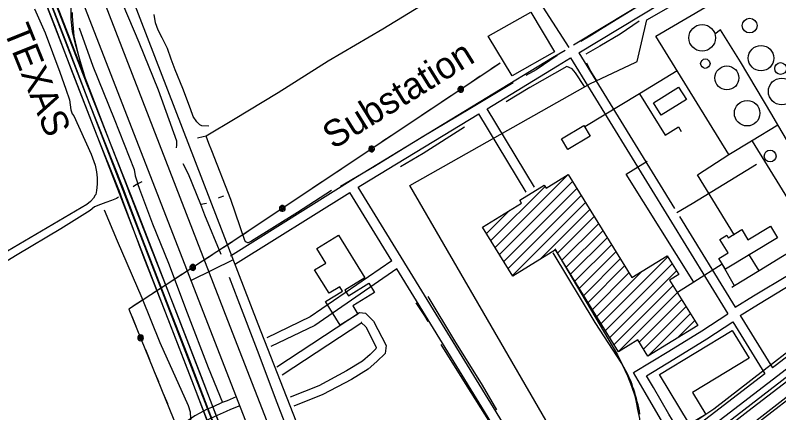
# Model space of a CAD drawing. Extents: x 3297753 to 3335611, y 652252 to 677623.
# Drawn here: x 3303720 to 3306096, y 667532 to 668771 of the extents above; entities that cross this region are included whole.
import ezdxf

# ---------------------------------------------------------------- set-up
doc = ezdxf.new("R2010")
doc.units = 0
for name, color, linetype in [('V-BLDG-OTLN', 7, 'Continuous'), ('V-DOMW-TANK', 7, 'Continuous'), ('V-DTCH-CNTR', 7, 'Continuous'), ('V-RAIL-IDEN', 7, 'Continuous'), ('V-RAIL-TRAK', 7, 'Continuous'), ('V-ROAD-CNTR', 7, 'Continuous'), ('V-SITE-OTLN', 7, 'Continuous'), ('V-SITE-OTLN-IDEN', 7, 'Continuous'), ('V-TOPO-SHOR', 7, 'Continuous'), ('V-UTIL-LINE', 7, 'Continuous')]:
    doc.layers.add(name, color=color, linetype=linetype)

msp = doc.modelspace()

# ---------------------------------------------------------------- linework, layer by layer
at = {"layer": 'V-BLDG-OTLN'}
for p, q in [((3305214, 668047.3), (3305440.9, 668274.2)), ((3305227.5, 668025.4), (3305454.5, 668252.4)), ((3305200.5, 668069.1), (3305369, 668237.6)), ((3305241, 668003.6), (3305468, 668230.6)), ((3305254.5, 667981.7), (3305481.5, 668208.7)), ((3305290.2, 668194.2), (3305290.4, 668194.4)), ((3305268, 667959.9), (3305495, 668186.9)), ((3305187, 668091), (3305259.2, 668163.2)), ((3305354.9, 668011.5), (3305508.5, 668165)), ((3305408, 668029.2), (3305522, 668143.2)), ((3305421.5, 668007.3), (3305535.5, 668121.3)), ((3305435, 667985.5), (3305549, 668099.5)), ((3305448.5, 667963.7), (3305562.5, 668077.7)), ((3305462.1, 667941.8), (3305576.1, 668055.8)), ((3305475.6, 667920), (3305589.6, 668034)), ((3305489.1, 667898.1), (3305603.1, 668012.1)), ((3305543.1, 667810.7), (3305750.8, 668018.4)), ((3305502.6, 667876.3), (3305616.6, 667990.3)), ((3305556.6, 667788.9), (3305764.3, 667996.6)), ((3305516.1, 667854.4), (3305630.1, 667968.4)), ((3305529.6, 667832.6), (3305669.8, 667972.7)), ((3305570.1, 667767), (3305777.8, 667974.7)), ((3305583.6, 667745.2), (3305767.2, 667928.8)), ((3305597.1, 667723.3), (3305780.8, 667907)), ((3305661.8, 667752.6), (3305794.3, 667885.1)), ((3305675.3, 667730.8), (3305807.8, 667863.3)), ((3305688.8, 667708.9), (3305821.3, 667841.4)), ((3305780.1, 667764.9), (3305834.8, 667819.6))]:
    msp.add_line(p, q, dxfattribs=at)
for points in [[(3305706.2, 668497.7), (3305784.5, 668546.8), (3305808.8, 668508), (3305730.6, 668458.9)], [(3305420, 668385.5), (3305489.1, 668427), (3305509.2, 668393.6), (3305440.1, 668352.1)], [(3305597.7, 667722.5), (3305401.3, 668040.1), (3305269, 667958.3), (3305174.6, 668110.9), (3305295.5, 668185.7), (3305290.2, 668194.3), (3305366.6, 668241.5), (3305372.5, 668231.9), (3305441, 668274.3), (3305639.1, 667953.8), (3305748.8, 668021.6), (3305784.9, 667963.2), (3305756.7, 667945.8), (3305844.1, 667804.5), (3305689, 667708.6), (3305657.5, 667759.5)], [(3306092.6, 668077.6), (3305930.4, 667979.6), (3305910.3, 668012.9), (3305938.6, 668030.1), (3305913.2, 668072.2), (3305934.8, 668085.2), (3305939.4, 668077.5), (3305981.2, 668102.7), (3306000.4, 668070.8), (3306071, 668113.4)], [(3304726.2, 668085.6), (3304807.9, 667952.7), (3304745.6, 667914.3), (3304756.5, 667896.6), (3304819.9, 667935.6), (3304837.6, 667906.8), (3304770, 667865.2), (3304785.8, 667839.4), (3304731, 667805.7), (3304685.9, 667879.1), (3304738.4, 667911.4), (3304729.9, 667925.1), (3304696.4, 667904.5), (3304651.6, 667977.3), (3304686.3, 667998.7), (3304658.5, 668044)], [(3305818.8, 667496.6), (3305725.2, 667651.3), (3305951.8, 667788.4), (3306003.8, 667702.4), (3305827.6, 667595.8), (3305869.2, 667527.1)]]:
    msp.add_lwpolyline(points, close=True, dxfattribs=at)
at = {"layer": 'V-DOMW-TANK'}
for centre, radius in [((3305858, 668700.3), 41.6), ((3306005.8, 668738.4), 22.9), ((3306041.3, 668636.9), 39.7), ((3305867.8, 668619.8), 14.6), ((3306102.1, 668604.6), 18.4), ((3305935, 668575.3), 37.2), ((3306105.9, 668533.1), 41.8), ((3305998, 668465.4), 39.7), ((3306069.6, 668332), 18.4)]:
    msp.add_circle(centre, radius, dxfattribs=at)
at = {"layer": 'V-DTCH-CNTR'}
for points in [[(3303779.4, 668790.4), (3303812.6, 668716.3), (3303858.2, 668593.6), (3303877, 668539.8), (3303888.3, 668507), (3303892.7, 668476.2), (3303896.5, 668463.2), (3303901.5, 668457.1), (3303956, 668338.2), (3303968, 668303.4), (3303972.7, 668282.9), (3303974.7, 668264.4), (3303974.6, 668244.4), (3303972.4, 668225), (3303970, 668212.6), (3303968, 668209.8), (3303963.4, 668201.3), (3303953.4, 668190), (3303942.7, 668180.8), (3303659, 668014.6)], [(3304322.1, 668424.9), (3304300.8, 668425.7), (3304294.5, 668428.9), (3304284.5, 668438.3), (3304273.7, 668455.1), (3304264.8, 668479), (3304240.9, 668542.3), (3304217.8, 668600.8), (3304205.1, 668634.1), (3304193.1, 668666.8), (3304177, 668700.1), (3304164.6, 668724.5), (3304156.4, 668747), (3304152.2, 668773)], [(3304258.4, 667464.2), (3304267.1, 667496.1), (3304265.3, 667534.6), (3304259.2, 667553.8), (3304170.7, 667750.2), (3304114.3, 667889.8), (3304038.1, 668067.3), (3303997.4, 668163.9)]]:
    msp.add_lwpolyline(points, dxfattribs=at)
at = {"layer": 'V-RAIL-TRAK'}
for points in [[(3304384.4, 667339.6), (3304326.4, 667483.4), (3304269.2, 667633.7), (3304197.2, 667818.4), (3304121.2, 668014), (3304054.7, 668192.6), (3304042.9, 668224.2), (3304040.2, 668231.6), (3303974.5, 668395.2), (3303897.6, 668592.6), (3303841.3, 668740.2), (3303767.3, 668931.7)], [(3304416.9, 667342.4), (3304355.9, 667496.6), (3304299.2, 667644.1), (3304223.1, 667842.9), (3304145.2, 668040.3), (3304080.7, 668204.6), (3304079.7, 668207.1), (3304065.1, 668245.1), (3304016.1, 668371.1), (3303940.5, 668568.6), (3303928.3, 668599.8), (3303865.6, 668760.1), (3303793, 668948.4)], [(3303794.8, 668900.7), (3303880.9, 668677), (3303949, 668499.5), (3304026.8, 668303.5), (3304052, 668238), (3304066.9, 668199.7), (3304103.4, 668104.7), (3304184.9, 667892.8), (3304260.9, 667698.1), (3304336, 667502.5), (3304401, 667335.9)], [(3303896.3, 668779.1), (3303896.6, 668768.1), (3303898.8, 668741.8), (3303902.2, 668705.5), (3303914.8, 668652.6), (3303928.3, 668599.8)], [(3305465.3, 667062.8), (3305492.9, 667084.2), (3305566.3, 667140.9), (3305603.3, 667169.8), (3305672.4, 667223.8), (3305787.2, 667313.1), (3305900.4, 667401.1), (3306015.2, 667489.9), (3306133.9, 667580.6), (3306154.8, 667596.7), (3306238.5, 667661), (3306319.6, 667724.2), (3306404.8, 667791.6), (3306514.7, 667881.2), (3306650.8, 667984.9), (3306796.5, 668095.6), (3306905.1, 668178.3), (3307023.4, 668268), (3307044.4, 668284.5), (3307106.5, 668333.1)], [(3305664.2, 667528.2), (3305662.5, 667537.9), (3305660.5, 667547.6), (3305658.4, 667557.2), (3305656.1, 667566.7), (3305653.6, 667576.3), (3305650.9, 667585.7), (3305648, 667595.1), (3305644.9, 667604.5), (3305642.3, 667612.5), (3305639.6, 667620.5), (3305636.6, 667628.3), (3305633.5, 667636.2), (3305630.2, 667643.9), (3305626.7, 667651.6), (3305607.4, 667685.5), (3305524.5, 667813.3), (3305394.1, 668030.4)], [(3305603.3, 667169.8), (3305625.3, 667191.1), (3305647.2, 667212.5), (3305668.9, 667234.1), (3305690.4, 667255.8), (3305711.9, 667277.6), (3305733.1, 667299.6), (3305754.3, 667321.7), (3305775.3, 667344), (3305796.1, 667366.4), (3305804.2, 667375.2), (3305812.5, 667383.8), (3305820.9, 667392.3), (3305829.5, 667400.7), (3305838.2, 667408.9), (3305847.1, 667416.9), (3305856.1, 667424.8), (3305865.3, 667432.5), (3305874.6, 667440), (3305884, 667447.3), (3305893.6, 667454.5), (3305999.7, 667537.8), (3306155.7, 667656.5)]]:
    msp.add_lwpolyline(points, dxfattribs=at)
at = {"layer": 'V-ROAD-CNTR'}
for points in [[(3306005.5, 663196.3), (3304715.5, 666525.6), (3304323.1, 667532.4), (3303700.3, 669143.4), (3302983.3, 670989.4), (3302517.9, 672183.2), (3302128.4, 673187.7), (3301925.1, 673723.4), (3301858.5, 673891.5)], [(3301858.5, 673843), (3302110.4, 673192.6), (3302969.1, 670977.7), (3303699.5, 669104.9), (3304312.1, 667521.8), (3304841.2, 666157.3), (3305391.9, 664734.2), (3306004.5, 663141.9)], [(3305457, 668678), (3306172.5, 669110.8), (3306275, 669172.3)], [(3304518.1, 667083.6), (3304339.4, 667538), (3304092.6, 668177.4), (3303929.7, 668588.8), (3303721.8, 669127.7)], [(3305473.9, 668653.2), (3306188, 669085.1), (3306212.6, 669099.8)], [(3303879.6, 668942), (3304456.2, 667456.8), (3304976.4, 666107.5), (3305633.2, 664416.3), (3306092.2, 663227.5)], [(3303947.7, 668939), (3304387.9, 667802.2), (3304786.3, 666778.2), (3305309.3, 665446.5), (3305940.2, 663811.2), (3306168.7, 663220.3)], [(3304044.5, 668926.8), (3304474.4, 667809.3), (3304892, 666744), (3305350.6, 665585.9), (3305492.3, 665228.1), (3306227.1, 663289)], [(3305443.5, 668669.9), (3305363.3, 668795.6), (3305316.3, 668867.9)], [(3303945.6, 668548.5), (3303923, 668625.7), (3303907.5, 668680.8), (3303897.4, 668719.8), (3303893.3, 668758), (3303893.6, 668799.4)], [(3304389.8, 668021.3), (3304779.3, 668265.3), (3305391.6, 668638.5), (3305431, 668662.3)], [(3305473.9, 668653.2), (3305771.7, 668168.6)], [(3305188.2, 668479.4), (3305407.2, 668612.9), (3305448.2, 668637.7)], [(3305448.2, 668637.7), (3305938.1, 667840.5)], [(3304786.7, 668234.6), (3304795.1, 668239.8), (3305162.6, 668463.8)], [(3305310.5, 668219.5), (3305162.6, 668463.8)], [(3305336.2, 668235), (3305188.2, 668479.4)], [(3307110.5, 668347), (3306146.4, 667600.8), (3305586.6, 667165), (3305487.1, 667091.2), (3305258.5, 666911), (3305232.9, 666890), (3305201, 666869), (3305164.3, 666846.3), (3305121.5, 666825.1), (3305084.9, 666810.9), (3305041.5, 666799.3), (3304993.6, 666791.7), (3304958, 666788.4), (3304921.3, 666789.3), (3304873.1, 666793.6), (3304819, 666807.8), (3304773.9, 666822.9), (3304731.6, 666842.2), (3304681, 666873.6), (3304643.2, 666904), (3304610.2, 666938.1), (3304573.3, 666983.1), (3304515.5, 667090.1)], [(3305779.3, 668156.2), (3305826.6, 668184.1), (3305944.6, 668255.9), (3306026.9, 668307.2)], [(3307022.5, 668278.9), (3306963.4, 668244.4), (3306934.2, 668227.6), (3306853.8, 668182), (3306805.6, 668156.9), (3306779.4, 668144.4), (3306758, 668131.8), (3306723.6, 668106.4), (3306388.4, 667849.4), (3305869.9, 667449.3), (3305848.1, 667431.2), (3305832, 667415.5), (3305638.6, 667212.6), (3305586.6, 667165)], [(3304405.7, 667995.9), (3304761.3, 668218.7)], [(3304892.2, 668005.8), (3304761.3, 668218.7)], [(3305773.7, 667439.3), (3305496.3, 667226.1), (3305474.4, 667211.5), (3305448.2, 667205.4), (3305432.4, 667208.8), (3305417.5, 667220.3), (3305398.5, 667239.6), (3304786.7, 668234.6)], [(3306846.5, 668227.5), (3306107.2, 667657.8), (3305513.8, 667201.6), (3305486.5, 667183.5), (3305448.5, 667174.6), (3305419.4, 667180.9), (3305397.6, 667197.8), (3305374.7, 667221), (3305269.1, 667392.7)], [(3305786.9, 668143.8), (3305960.6, 667861.2)], [(3305960.7, 667861.1), (3306017.7, 667896.3), (3306128.6, 667963), (3306263.1, 668053.4), (3306321.8, 667963.3), (3306358.5, 667901.2), (3306363.3, 667893)], [(3305399.2, 668043.1), (3305594.1, 667713.2), (3305608, 667685.3), (3305625.1, 667647.5), (3305637.6, 667615.7), (3305648.4, 667584.9), (3305653.7, 667560.3), (3305656.7, 667542.6), (3305663, 667514.5), (3305665.8, 667479.7), (3305667.4, 667448.2), (3305665.2, 667415.6), (3305662.7, 667380.5), (3305657.4, 667347.6), (3305647.5, 667315.5), (3305634.7, 667282.9), (3305611.6, 667238.3), (3305591.7, 667205.2), (3305573.9, 667177.8), (3305550.9, 667149.8), (3305505.6, 667104.9)], [(3304397.8, 668008.6), (3304267.1, 667943.9)], [(3304892.2, 668005.8), (3304637.4, 667830.7), (3304502.6, 667765.9)], [(3305976.4, 667835.5), (3306033.3, 667870.7), (3306144.7, 667937.7), (3306254.6, 668011.5), (3306296.3, 667947.5), (3306332.6, 667885.9), (3306339.4, 667874.6)], [(3304907.9, 667980.2), (3304652.5, 667804.7), (3304515.6, 667738.8)], [(3305253.4, 667418.3), (3304907.9, 667980.2)], [(3306339.7, 667874.9), (3306088.9, 667681.5), (3306076.7, 667672.2)], [(3304534.2, 667675.8), (3304790.9, 667844.8), (3304810.1, 667842.3), (3304835.2, 667818.1), (3304874.1, 667742), (3304870.7, 667717), (3304845, 667691.8), (3304818.5, 667668.5), (3304766, 667636.4), (3304677.5, 667589.5), (3304586.6, 667553.3)], [(3305773.3, 667439), (3305762.8, 667456.8), (3305727.9, 667513.2), (3305680.8, 667595.9), (3305643.8, 667657.5), (3305753.9, 667724.5), (3305856.6, 667787.8), (3305937.8, 667841)], [(3305797.3, 667457.4), (3305788.5, 667472.4), (3305753.7, 667528.5), (3305706.7, 667611.1), (3305684.9, 667647.4), (3305769.6, 667699), (3305872.7, 667762.5), (3305953.5, 667815.4)], [(3305953.5, 667815.4), (3306052.8, 667653.8)], [(3305976.2, 667835.8), (3306076.7, 667672.2)], [(3304550.7, 667650.7), (3304798.2, 667813.6), (3304796.5, 667813.8), (3304810.8, 667800), (3304843.1, 667736.7), (3304842.3, 667731.2), (3304824.5, 667713.8), (3304800.6, 667692.7), (3304751.1, 667662.5), (3304664.9, 667616.7), (3304575.5, 667581.2)], [(3306052.8, 667653.8), (3305797.3, 667457.4)], [(3304407.2, 667581.9), (3304378.8, 667570), (3304364.2, 667564.3), (3304335.8, 667551.3), (3304314.6, 667542.2), (3304293.9, 667531.5), (3304278.9, 667522.6), (3304258.2, 667508.4), (3304244, 667490.2)], [(3304418.9, 667554.2), (3304390.1, 667542.1), (3304375.9, 667536.7), (3304348, 667523.9), (3304327.4, 667515), (3304308.4, 667505.3), (3304295, 667497.4), (3304279, 667486.3), (3304274.5, 667480.5), (3304274.5, 667479.4), (3304278.8, 667472.1), (3304292, 667452.2), (3304306.8, 667427.1), (3304321.2, 667398.8), (3304336.5, 667363.4), (3304362.5, 667302.9), (3304382.3, 667247.9), (3304468.6, 666991), (3304475, 666975.9)]]:
    msp.add_lwpolyline(points, dxfattribs=at)
at = {"layer": 'V-SITE-OTLN'}
for points in [[(3306424.2, 669192.9), (3306471.9, 669223.4), (3306805.5, 669421.9), (3307056.7, 669013.6), (3307188.7, 668799.1), (3307266.1, 668633.2), (3306935.3, 668353.3), (3306768.7, 668226.8), (3306728.6, 668196.3), (3306345.6, 667893.6), (3306308, 667864), (3306051.2, 667665.2), (3305894.2, 667543.8), (3305775.6, 667464.6), (3305667.2, 667392.2), (3305643.3, 667376.2), (3305496, 667294.9), (3304948.2, 668240.5), (3305509.9, 668558.1), (3305649.2, 668623.5), (3305655.6, 668626.4), (3305686.1, 668756.4), (3306224.5, 669065), (3306245.2, 669078.3)], [(3305266.8, 668581.8), (3305192.2, 668705.3), (3305324.6, 668780.5), (3305397.9, 668656.6)]]:
    msp.add_lwpolyline(points, close=True, dxfattribs=at)
at = {"layer": 'V-TOPO-SHOR'}
for p, q in [((3305661.5, 668751.7), (3305602.6, 668711.9)), ((3304315, 668184.6), (3304296.9, 668181))]:
    msp.add_line(p, q, dxfattribs=at)
for points in [[(3305513.9, 669124.1), (3305382.9, 669043.9), (3305355.3, 669027.1), (3305200.1, 668933.9), (3305024.1, 668825.7), (3304863.9, 668727.6), (3304693.8, 668627.1), (3304538.4, 668528.8), (3304399, 668444.6), (3304318.7, 668396.9), (3304314, 668393.7), (3304304.8, 668392.1), (3304287, 668387.4)], [(3303979, 669006), (3304037.2, 668846.7), (3304104.8, 668686.6), (3304164.5, 668538), (3304221.4, 668379.3), (3304221.4, 668365.9), (3304220.3, 668357.3)], [(3306020, 669016.9), (3305789.1, 668879.8), (3305550, 668731.6)], [(3303918.3, 668731.2), (3303960.9, 668612.2), (3304027.2, 668448.3), (3304089.3, 668289.8), (3304092.6, 668270.7), (3304101.6, 668245.2)], [(3305550, 668731.6), (3305513.3, 668708.5), (3305479.9, 668688.7)], [(3305602.6, 668711.9), (3305539.2, 668674), (3305496.3, 668649.4)], [(3305406.7, 668645.3), (3305341.7, 668600.4), (3305308.6, 668583.3)], [(3305436.6, 668611.2), (3305321.8, 668545), (3305248.3, 668500.6)], [(3305491.7, 668548.7), (3305463.7, 668591.4), (3305453.7, 668603.5), (3305436.6, 668611.2)], [(3305530, 668566.3), (3305511.2, 668596.6), (3305498.5, 668621.3)], [(3305269.4, 668559.8), (3305135.1, 668479.3), (3304986.3, 668390.8), (3304837.9, 668299.2), (3304731.9, 668237)], [(3305117.7, 668421.5), (3304989.6, 668339.8), (3304919.1, 668298.6)], [(3304704.5, 668224.5), (3304598.3, 668155.8), (3304454.7, 668066.4), (3304444.5, 668061.3), (3304443.2, 668061.6), (3304437.2, 668064.5), (3304434.4, 668069.2), (3304390.8, 668196.7), (3304331.3, 668348.1), (3304322.1, 668371.5), (3304314, 668393.7)], [(3304360.2, 668025.2), (3304310.3, 668147.4), (3304296.9, 668181), (3304259.4, 668275.3), (3304242.3, 668308.1)], [(3304113.5, 668252.1), (3304101.6, 668245.2), (3304091.2, 668239.1), (3304086.3, 668236.2)], [(3304366.3, 667563.2), (3304320.9, 667672.4), (3304256.1, 667842.6), (3304197.9, 667997.4), (3304147.6, 668119.7), (3304113.4, 668210.7), (3304107.1, 668227.8), (3304101.6, 668245.2)], [(3304040.8, 668203.5), (3304034.7, 668199.7), (3304019.1, 668193.7), (3304001.1, 668187.7), (3303984.8, 668181), (3303966.5, 668173.3), (3303952.7, 668162.2), (3303861, 668105.6), (3303725.7, 668024.7), (3303569.2, 667929.1), (3303441.3, 667851.1), (3303269.6, 667745.5), (3303138.1, 667665), (3302997.8, 667578.8), (3302981.9, 667570.4)], [(3304367.9, 668206.8), (3304356.7, 668202.7), (3304350.9, 668200.8)], [(3304628, 667318.6), (3304593.3, 667411.6), (3304585.6, 667431.6), (3304534.6, 667563.7), (3304473.8, 667726.4), (3304413.2, 667882.9), (3304386.7, 667953.2)], [(3305003.8, 667894.9), (3305086.5, 667756.5), (3305172.7, 667618.6), (3305217.5, 667541)], [(3304967, 667874.5), (3304993.6, 667834.8), (3305004.4, 667816.6)], [(3305044.6, 667745), (3305120.3, 667623.2), (3305198.2, 667499.9), (3305232.6, 667439.8)]]:
    msp.add_lwpolyline(points, dxfattribs=at)
at = {"layer": 'V-UTIL-LINE'}
msp.add_line((3306035.6, 667974.5), (3306003.5, 668026.4), dxfattribs=at)
for points in [[(3305958.8, 668086), (3305843.6, 668273.6), (3305941.2, 668336.7), (3305713.6, 668705.5), (3306201.3, 668992.1), (3306223, 668952)], [(3306281, 668123.4), (3306180.9, 668281.7), (3306150.8, 668332.5), (3306093.5, 668429.3), (3306074.5, 668461.3), (3305977.5, 668625.7), (3305915.4, 668724.7), (3305897.3, 668711.5)], [(3305228.8, 668621.4), (3304415.9, 668078.4), (3304073.5, 667855.5), (3305027.9, 665506.4)], [(3305228.8, 668621.4), (3305200.5, 668602.6)], [(3305167.3, 668580.3), (3305139, 668561.5)], [(3305780.4, 668597.3), (3305662.9, 668525.9), (3305493, 668422.5)], [(3305106.6, 668539.8), (3305109.2, 668538.7), (3305108.7, 668541), (3305106.1, 668541.9), (3305103.9, 668540.1), (3305105.6, 668537.1), (3305110.2, 668536.1), (3305112.4, 668539.7), (3305110.9, 668544.4), (3305106.5, 668545.5), (3305102.3, 668543.9), (3305100.9, 668539.2), (3305103.7, 668534.5), (3305111.6, 668532.3), (3305114, 668534.8), (3305115.4, 668538), (3305115.4, 668541.5), (3305114, 668544.8), (3305111.6, 668547.3), (3305108.3, 668548.6), (3305104.8, 668548.6), (3305101.6, 668547.3), (3305099.1, 668544.8), (3305097.7, 668541.5), (3305097.7, 668538), (3305099.1, 668534.8), (3305101.6, 668532.3), (3305104.8, 668531), (3305108.3, 668531), (3305111.6, 668532.3)], [(3305074.1, 668518.1), (3305045.9, 668499.2)], [(3305662.9, 668525.9), (3305743.3, 668396.6), (3305784.5, 668423), (3305793, 668408.8)], [(3305012.6, 668477), (3304984.3, 668458.1)], [(3304951.1, 668435.9), (3304922.8, 668417)], [(3305941.2, 668336.7), (3306011.2, 668379), (3306093.5, 668429.3)], [(3304889.5, 668394.8), (3304861.3, 668375.9)], [(3304828.8, 668354.2), (3304831.5, 668353.2), (3304831, 668355.4), (3304828.4, 668356.4), (3304826.2, 668354.5), (3304827.9, 668351.6), (3304832.5, 668350.6), (3304834.7, 668354.2), (3304833.2, 668358.8), (3304828.7, 668359.9), (3304824.6, 668358.3), (3304823.2, 668353.7), (3304826, 668348.9), (3304833.8, 668346.8), (3304836.3, 668349.2), (3304837.7, 668352.5), (3304837.7, 668356), (3304836.3, 668359.2), (3304833.8, 668361.7), (3304830.6, 668363.1), (3304827.1, 668363.1), (3304823.8, 668361.7), (3304821.4, 668359.2), (3304820, 668356), (3304820, 668352.5), (3304821.4, 668349.2), (3304823.8, 668346.8), (3304827.1, 668345.4), (3304830.6, 668345.4), (3304833.8, 668346.8)], [(3306201.1, 668074.9), (3306014.5, 668378.1), (3306011.2, 668379)], [(3304796.4, 668332.6), (3304768.1, 668313.7)], [(3305831.7, 667939.5), (3305621.7, 668275.1), (3305686.5, 668316.3)], [(3304734.9, 668291.5), (3304706.6, 668272.6)], [(3304673.3, 668250.4), (3304645.1, 668231.5)], [(3304611.8, 668209.3), (3304583.5, 668190.4)], [(3306569.3, 667932.5), (3306568.5, 667937.3), (3306492, 668061.6), (3306407, 668199.9), (3306281, 668123.4), (3306201.1, 668074.9), (3306108.5, 668018.7), (3306035.6, 667974.5), (3305958.5, 667927.7), (3305950.7, 667923)], [(3304551.1, 668168.7), (3304553.8, 668167.6), (3304553.2, 668169.9), (3304550.7, 668170.9), (3304548.4, 668169), (3304550.2, 668166.1), (3304554.8, 668165), (3304557, 668168.7), (3304555.5, 668173.3), (3304551, 668174.4), (3304546.9, 668172.8), (3304545.5, 668168.2), (3304548.3, 668163.4), (3304556.1, 668161.2), (3304558.6, 668163.7), (3304559.9, 668166.9), (3304559.9, 668170.5), (3304558.6, 668173.7), (3304556.1, 668176.2), (3304552.9, 668177.5), (3304549.4, 668177.5), (3304546.1, 668176.2), (3304543.6, 668173.7), (3304542.3, 668170.5), (3304542.3, 668166.9), (3304543.6, 668163.7), (3304546.1, 668161.2), (3304549.4, 668159.9), (3304552.9, 668159.9), (3304556.1, 668161.2)], [(3304518.7, 668147), (3304490.4, 668128.2)], [(3304457.2, 668105.9), (3304428.9, 668087)], [(3304395.5, 668065.1), (3304367, 668046.5)], [(3304333.5, 668024.7), (3304305, 668006.1)], [(3304272.3, 667984.9), (3304274.9, 667983.8), (3304274.4, 667986), (3304271.9, 667987), (3304269.6, 667985.2), (3304271.3, 667982.2), (3304275.9, 667981.1), (3304278.1, 667984.8), (3304276.7, 667989.4), (3304272.2, 667990.6), (3304268.1, 667989), (3304266.6, 667984.4), (3304269.3, 667979.6), (3304277.2, 667977.3), (3304279.7, 667979.8), (3304281.1, 667983), (3304281.1, 667986.5), (3304279.8, 667989.8), (3304277.4, 667992.3), (3304274.1, 667993.7), (3304270.6, 667993.7), (3304267.4, 667992.4), (3304264.8, 667990), (3304263.5, 667986.7), (3304263.4, 667983.2), (3304264.7, 667980), (3304267.2, 667977.4), (3304270.4, 667976.1), (3304273.9, 667976), (3304277.2, 667977.3)], [(3305958.5, 667927.7), (3305920.4, 667995.2), (3305831.7, 667939.5), (3305780.7, 667907.4)], [(3304239.6, 667963.6), (3304211.1, 667945)], [(3304177.6, 667923.2), (3304149.1, 667904.7)], [(3304115.6, 667882.8), (3304087.1, 667864.3)], [(3304082.5, 667833.4), (3304095.3, 667801.9)], [(3304110, 667765.8), (3304111.5, 667768.2), (3304109.2, 667768.1), (3304107.8, 667765.8), (3304109.2, 667763.2), (3304112.4, 667764.3), (3304114.3, 667768.6), (3304111.2, 667771.5), (3304106.4, 667770.9), (3304104.4, 667766.8), (3304105.1, 667762.4), (3304109.4, 667760.1), (3304114.6, 667761.9), (3304118.3, 667769.1), (3304116.4, 667772.1), (3304113.5, 667774), (3304110, 667774.8), (3304106.6, 667774.1), (3304103.6, 667772.2), (3304101.7, 667769.3), (3304101, 667765.8), (3304101.6, 667762.4), (3304103.6, 667759.4), (3304106.5, 667757.5), (3304109.9, 667756.8), (3304113.4, 667757.4), (3304116.3, 667759.3), (3304118.3, 667762.3), (3304119, 667765.7), (3304118.3, 667769.1)], [(3304124.6, 667729.6), (3304137.4, 667698.1)], [(3304152.5, 667661.1), (3304165.3, 667629.6)], [(3304180.4, 667592.5), (3304193.1, 667561)]]:
    msp.add_lwpolyline(points, dxfattribs=at)

# ---------------------------------------------------------------- texts
at = {"layer": 'V-RAIL-IDEN'}
msp.add_text('TEXAS', height=83, rotation=291.9088, dxfattribs=at).set_placement((3303682.3, 668723.4))
at = {"layer": 'V-SITE-OTLN-IDEN'}
msp.add_text('Substation', height=83, rotation=31.766, dxfattribs=at).set_placement((3304709.6, 668351.2))

doc.saveas('drawing.dxf')
